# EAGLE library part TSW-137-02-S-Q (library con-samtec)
THROUGH-HOLE .025" SQ POST HEADER Source: Samtec TSW.pdf
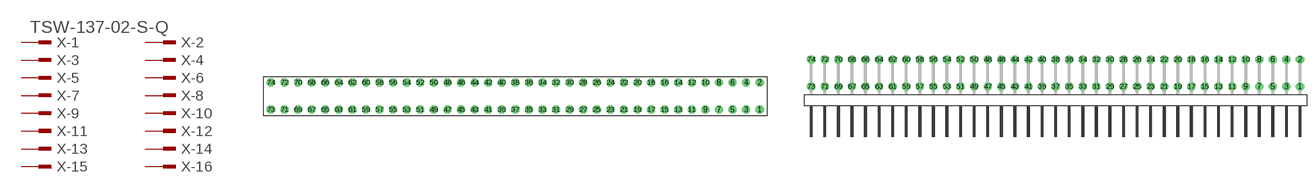
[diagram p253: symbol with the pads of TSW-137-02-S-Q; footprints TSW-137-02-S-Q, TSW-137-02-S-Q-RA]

Designator prefix X; gates -1=MPINV -2=MPIN -3=MPIN -4=MPIN -5=MPIN -6=MPIN -7=MPIN -8=MPIN -9=MPIN -10=MPIN -11=MPIN -12=MPIN -13=MPIN -14=MPIN -15=MPIN -16=MPIN -17=MPIN -18=MPIN -19=MPIN -20=MPIN -21=MPIN -22=MPIN -23=MPIN -24=MPIN -25=MPIN -26=MPIN -27=MPIN -28=MPIN -29=MPIN -30=MPIN -31=MPIN -32=MPIN -33=MPIN -34=MPIN -35=MPIN -36=MPIN -37=MPIN -38=MPIN -39=MPIN -40=MPIN -41=MPIN -42=MPIN -43=MPIN -44=MPIN -45=MPIN -46=MPIN -47=MPIN -48=MPIN -49=MPIN -50=MPIN -51=MPIN -52=MPIN -53=MPIN -54=MPIN -55=MPIN -56=MPIN -57=MPIN -58=MPIN -59=MPIN -60=MPIN -61=MPIN -62=MPIN -63=MPIN -64=MPIN -65=MPIN -66=MPIN -67=MPIN -68=MPIN -69=MPIN -70=MPIN -71=MPIN -72=MPIN -73=MPIN -74=MPIN

## TSW-137-02-S-Q (OC_FARNELL: unknown; OC_NEWARK: unknown)  [TSW-137-02-S-Q]
1  -1:1  pas
2  -2:1  pas
3  -3:1  pas
4  -4:1  pas
5  -5:1  pas
6  -6:1  pas
7  -7:1  pas
8  -8:1  pas
9  -9:1  pas
10  -10:1  pas
11  -11:1  pas
12  -12:1  pas
13  -13:1  pas
14  -14:1  pas
15  -15:1  pas
16  -16:1  pas
17  -17:1  pas
18  -18:1  pas
19  -19:1  pas
20  -20:1  pas
21  -21:1  pas
22  -22:1  pas
23  -23:1  pas
24  -24:1  pas
25  -25:1  pas
26  -26:1  pas
27  -27:1  pas
28  -28:1  pas
29  -29:1  pas
30  -30:1  pas
31  -31:1  pas
32  -32:1  pas
33  -33:1  pas
34  -34:1  pas
35  -35:1  pas
36  -36:1  pas
37  -37:1  pas
38  -38:1  pas
39  -39:1  pas
40  -40:1  pas
41  -41:1  pas
42  -42:1  pas
43  -43:1  pas
44  -44:1  pas
45  -45:1  pas
46  -46:1  pas
47  -47:1  pas
48  -48:1  pas
49  -49:1  pas
50  -50:1  pas
51  -51:1  pas
52  -52:1  pas
53  -53:1  pas
54  -54:1  pas
55  -55:1  pas
56  -56:1  pas
57  -57:1  pas
58  -58:1  pas
59  -59:1  pas
60  -60:1  pas
61  -61:1  pas
62  -62:1  pas
63  -63:1  pas
64  -64:1  pas
65  -65:1  pas
66  -66:1  pas
67  -67:1  pas
68  -68:1  pas
69  -69:1  pas
70  -70:1  pas
71  -71:1  pas
72  -72:1  pas
73  -73:1  pas
74  -74:1  pas

## TSW-137-02-S-Q-RA (OC_FARNELL: unknown; OC_NEWARK: unknown)  [TSW-137-02-S-Q-RA]
Pads as for TSW-137-02-S-Q

## Footprint TSW-137-02-S-Q (pad centres in mm)
THROUGH-HOLE .025" SQ POST HEADER Source: Samtec TSW.pdf
drill 1 pad 1.5 octagon: 1 45.72,-2.54; 2 45.72,2.54; 3 43.18,-2.54; 4 43.18,2.54; 5 40.64,-2.54; 6 40.64,2.54; 7 38.1,-2.54; 8 38.1,2.54; 9 35.56,-2.54; 10 35.56,2.54; 11 33.02,-2.54; 12 33.02,2.54; 13 30.48,-2.54; 14 30.48,2.54; 15 27.94,-2.54; 16 27.94,2.54; 17 25.4,-2.54; 18 25.4,2.54; 19 22.86,-2.54; 20 22.86,2.54; 21 20.32,-2.54; 22 20.32,2.54; 23 17.78,-2.54; 24 17.78,2.54; 25 15.24,-2.54; 26 15.24,2.54; 27 12.7,-2.54; 28 12.7,2.54; 29 10.16,-2.54; 30 10.16,2.54; 31 7.62,-2.54; 32 7.62,2.54; 33 5.08,-2.54; 34 5.08,2.54; 35 2.54,-2.54; 36 2.54,2.54; 37 0,-2.54; 38 0,2.54; 39 -2.54,-2.54; 40 -2.54,2.54; 41 -5.08,-2.54; 42 -5.08,2.54; 43 -7.62,-2.54; 44 -7.62,2.54; 45 -10.16,-2.54; 46 -10.16,2.54; 47 -12.7,-2.54; 48 -12.7,2.54; 49 -15.24,-2.54; 50 -15.24,2.54; 51 -17.78,-2.54; 52 -17.78,2.54; 53 -20.32,-2.54; 54 -20.32,2.54; 55 -22.86,-2.54; 56 -22.86,2.54; 57 -25.4,-2.54; 58 -25.4,2.54; 59 -27.94,-2.54; 60 -27.94,2.54; 61 -30.48,-2.54; 62 -30.48,2.54; 63 -33.02,-2.54; 64 -33.02,2.54; 65 -35.56,-2.54; 66 -35.56,2.54; 67 -38.1,-2.54; 68 -38.1,2.54; 69 -40.64,-2.54; 70 -40.64,2.54; 71 -43.18,-2.54; 72 -43.18,2.54; 73 -45.72,-2.54; 74 -45.72,2.54

## Footprint TSW-137-02-S-Q-RA (pad centres in mm)
THROUGH-HOLE .025" SQ POST HEADER Source: Samtec TSW.pdf
drill 1 pad 1.5 octagon: 1 45.72,1.524; 2 45.72,6.604; 3 43.18,1.524; 4 43.18,6.604; 5 40.64,1.524; 6 40.64,6.604; 7 38.1,1.524; 8 38.1,6.604; 9 35.56,1.524; 10 35.56,6.604; 11 33.02,1.524; 12 33.02,6.604; 13 30.48,1.524; 14 30.48,6.604; 15 27.94,1.524; 16 27.94,6.604; 17 25.4,1.524; 18 25.4,6.604; 19 22.86,1.524; 20 22.86,6.604; 21 20.32,1.524; 22 20.32,6.604; 23 17.78,1.524; 24 17.78,6.604; 25 15.24,1.524; 26 15.24,6.604; 27 12.7,1.524; 28 12.7,6.604; 29 10.16,1.524; 30 10.16,6.604; 31 7.62,1.524; 32 7.62,6.604; 33 5.08,1.524; 34 5.08,6.604; 35 2.54,1.524; 36 2.54,6.604; 37 0,1.524; 38 0,6.604; 39 -2.54,1.524; 40 -2.54,6.604; 41 -5.08,1.524; 42 -5.08,6.604; 43 -7.62,1.524; 44 -7.62,6.604; 45 -10.16,1.524; 46 -10.16,6.604; 47 -12.7,1.524; 48 -12.7,6.604; 49 -15.24,1.524; 50 -15.24,6.604; 51 -17.78,1.524; 52 -17.78,6.604; 53 -20.32,1.524; 54 -20.32,6.604; 55 -22.86,1.524; 56 -22.86,6.604; 57 -25.4,1.524; 58 -25.4,6.604; 59 -27.94,1.524; 60 -27.94,6.604; 61 -30.48,1.524; 62 -30.48,6.604; 63 -33.02,1.524; 64 -33.02,6.604; 65 -35.56,1.524; 66 -35.56,6.604; 67 -38.1,1.524; 68 -38.1,6.604; 69 -40.64,1.524; 70 -40.64,6.604; 71 -43.18,1.524; 72 -43.18,6.604; 73 -45.72,1.524; 74 -45.72,6.604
